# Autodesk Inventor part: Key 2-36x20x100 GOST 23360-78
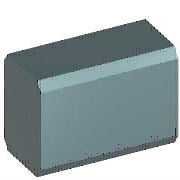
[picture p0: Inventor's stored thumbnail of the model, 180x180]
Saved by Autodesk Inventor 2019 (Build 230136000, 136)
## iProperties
Created: 2018-01
Part Number: Key 2-36x20x100 GOST 23360-78
Material: Steel, Mild
Description: Keyed joints with sunk keys
Document SubType Name: Modeling
Standard: GOST 23360-78 (2)
Designer: m.vorobev
Standards Organization: GOST
Language: en-US
Size Designation: 36 x 20 x 100
Categories: <MemberInstance><Categories><Category DisplayName="Shaft Parts" InternalName="7f7aeb1f-a693-4053-b835-cee3144e0d98" Mnemonic="SHFT"><Category DisplayName="Keys"
Density: 7.85 g/cm^3
Appearance: Semi-Polished
IsCustomPart: 1
Author: m.vorobev
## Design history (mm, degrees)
sketch "Sketch1"
  geometry: L1 (18, 18)-(44, 18); L2 (44, 18)-(44, -18); L3 (44, -18)-(18, -18); L4 (0, 25.2)-(0, -25.2) reference; L5 (-8.8, 0)-(52.8, 0) reference; L6 (18, 18)-(18, -18); A1 r 18 centre (18, 0) between (18, 18) and (18, -18)
  constraints: 8 end point, 3 tangent, 2 perpendicular, 2 point on circle, 1 centre point, 1 horizontal, 1 parallel, 1 point on line
  dimensions: "d0" = 18 radius of A1 (= 0.5 x PB); "d19" = 26 distance of L1.start L1.end
extrude "Body1" new body sketch "Sketch1" taper "d3" = 0 deg; stored distance "d4" = 10
body "Solid1"
workplane "Work Plane1"
workplane "Work Plane2"
chamfer "Chamfer1" distance "d8" = 1 (= PHH); stored, may be unused: second distance "d9" = 1 (= PHH), angle "d13" = 45 deg
other parameters: "d1" = -12 (= -PNT), "d2" = 8 (= PH - PNT), "PB" = 36 [user parameter; used in 1 equation term], "PNT" = 12 [user parameter; used in 2 equation terms], "PHH" = 1 [user parameter; used in 2 equation terms], "d10" = 0, "d16" = 0, "d17" = 0, "d18" = 0, "RR" = 0.7 [user parameter], "PLB1" = 118 [user parameter], "PLB2" = 136 [user parameter], "PUEB" = 8.4 [user parameter]
